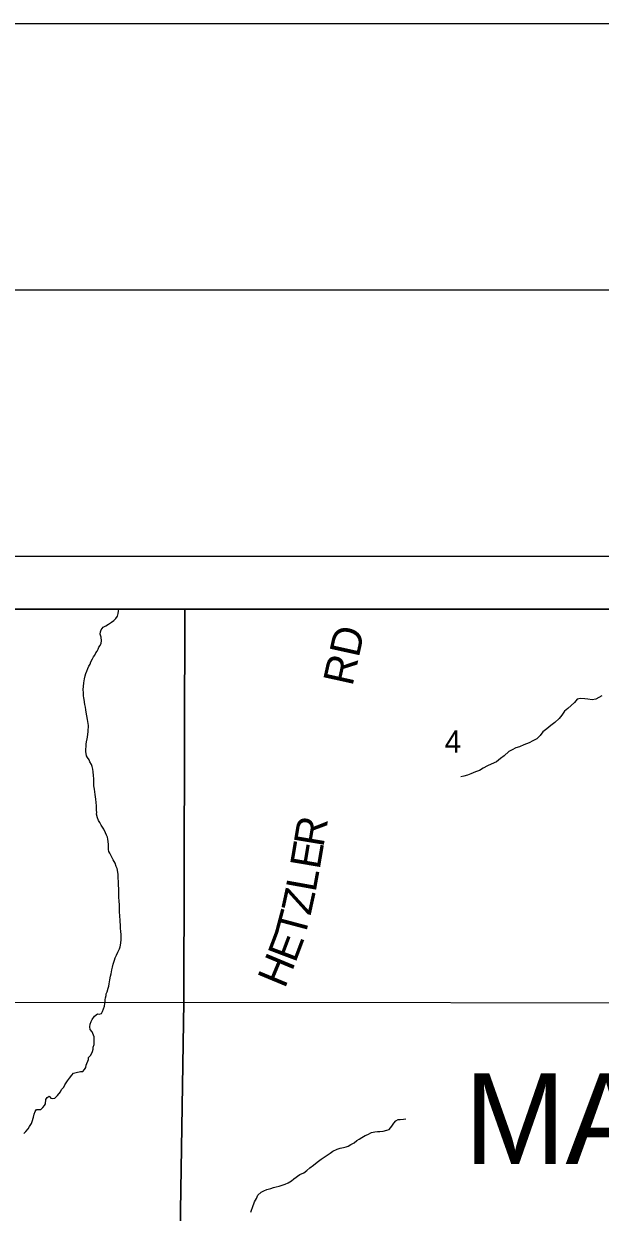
# Model space of a CAD drawing. Extents: x 0 to 34, y 0 to 22.
# Drawn here: x 3.881 to 4.964, y 19.765 to 21.998 of the extents above; entities that cross this region are included whole.
import ezdxf

# ---------------------------------------------------------------- set-up
doc = ezdxf.new("R2010")
doc.units = 0
for name, color, linetype in [('GM_X_Corporation', 7, 'Continuous'), ('GM_X_Minor_River', 7, 'Continuous'), ('GM_X_Section_Text', 7, 'Continuous'), ('GM_X_Township_Road_Text', 7, 'Continuous'), ('GM_X_Township_Text', 7, 'Continuous'), ('SH_Border', 7, 'Continuous'), ('SH_Cut_Line', 7, 'Continuous'), ('SH_Data', 7, 'Continuous')]:
    doc.layers.add(name, color=color, linetype=linetype)

msp = doc.modelspace()

# ---------------------------------------------------------------- linework, layer by layer
at = {"layer": 'GM_X_Corporation'}
msp.add_lwpolyline([(8.2346, 19.7113), (8.2412, 20.0451), (8.2424, 20.1172), (8.2437, 20.1914), (8.2459, 20.3463), (8.2498, 20.6242), (8.2532, 20.898), (2.1, 20.898)], dxfattribs=at)
for points in [[(4.1833, 20.898), (3.1749, 20.898), (3.1676, 20.1592), (4.1816, 20.1598)], [(5.1975, 20.898), (4.1833, 20.898), (4.1816, 20.1598), (5.1838, 20.1584)], [(3.1676, 20.1592), (4.1816, 20.1598), (4.1654, 19.1412), (3.1497, 19.1471)], [(5.1838, 20.1584), (5.1759, 19.1377), (4.1654, 19.1412), (4.1816, 20.1598)]]:
    msp.add_lwpolyline(points, close=True, dxfattribs=at)
at = {"layer": 'GM_X_Minor_River'}
for points in [[(4.0263, 20.8346), (4.0272, 20.8387), (4.0262, 20.8456), (4.0248, 20.8513), (4.0249, 20.8555), (4.0262, 20.8592), (4.0301, 20.8645), (4.0351, 20.867), (4.0405, 20.8699), (4.0456, 20.8739), (4.0499, 20.8772), (4.0541, 20.8809), (4.0573, 20.8853), (4.0586, 20.8899), (4.0591, 20.8948), (4.0594, 20.898)], [(4.0631, 20.293), (4.0628, 20.2987), (4.0626, 20.3037), (4.062, 20.312), (4.0621, 20.3154), (4.0615, 20.3204), (4.061, 20.3318), (4.0611, 20.3356), (4.0606, 20.3428), (4.06, 20.3497), (4.0598, 20.3572), (4.0593, 20.3652), (4.0595, 20.3736), (4.0592, 20.3789), (4.0587, 20.388), (4.0584, 20.3918), (4.0582, 20.396), (4.0583, 20.3998), (4.058, 20.404), (4.0563, 20.4109), (4.0549, 20.4147), (4.0524, 20.4208), (4.0491, 20.4274), (4.0455, 20.4351), (4.0426, 20.4397), (4.0411, 20.4432), (4.0405, 20.447), (4.0402, 20.4508), (4.0403, 20.4561), (4.0397, 20.4618), (4.0391, 20.4664), (4.0381, 20.4702), (4.0366, 20.4737), (4.0348, 20.4783), (4.0312, 20.4848), (4.0287, 20.4887), (4.0265, 20.4925), (4.0239, 20.4972), (4.0214, 20.5014), (4.0196, 20.5064), (4.0179, 20.5129), (4.018, 20.5163), (4.0177, 20.5209), (4.0179, 20.5288), (4.0169, 20.5353), (4.0163, 20.541), (4.015, 20.5498), (4.0138, 20.5601), (4.0128, 20.5662), (4.0126, 20.5715), (4.0124, 20.5795), (4.0122, 20.5856), (4.0116, 20.5928), (4.011, 20.5974), (4.0096, 20.6027), (4.0082, 20.6065), (4.0053, 20.6116), (4.0038, 20.6154), (4.0005, 20.6193), (3.9991, 20.6227), (3.9978, 20.6311), (3.9979, 20.6353), (3.998, 20.6402), (3.9981, 20.6444), (3.999, 20.6489), (3.9999, 20.6546), (4.0008, 20.658), (4.0022, 20.6682), (4.0025, 20.68), (4.0018, 20.6834), (4.0005, 20.691), (3.9995, 20.6979), (3.9982, 20.7048), (3.9975, 20.7089), (3.9969, 20.7139), (3.9959, 20.7189), (3.9942, 20.7284), (3.9936, 20.7318), (3.9933, 20.7356), (3.9931, 20.7413), (3.9928, 20.7474), (3.9934, 20.7531), (3.9939, 20.7599), (3.9944, 20.7637), (3.9953, 20.7675), (3.9965, 20.7728), (3.9978, 20.7777), (3.9998, 20.7818), (4.0015, 20.7867), (4.0035, 20.7912), (4.0055, 20.7949), (4.0071, 20.7994), (4.0103, 20.805), (4.0123, 20.8088), (4.0147, 20.8121), (4.0163, 20.8162), (4.0187, 20.8196), (4.0207, 20.823), (4.0223, 20.8267), (4.0243, 20.8301), (4.0263, 20.8346)], [(4.9407, 20.729), (4.9346, 20.7298), (4.9267, 20.7306), (4.9203, 20.7292), (4.9153, 20.7231), (4.9092, 20.7171), (4.9031, 20.7115), (4.8963, 20.7066), (4.8913, 20.6991), (4.8867, 20.693), (4.8783, 20.6851), (4.8707, 20.6795), (4.8631, 20.6735), (4.8559, 20.6675), (4.8506, 20.6611), (4.8445, 20.6547), (4.8369, 20.6506), (4.83, 20.6472), (4.8202, 20.6432), (4.8118, 20.6398), (4.8054, 20.6376), (4.7982, 20.6343), (4.7921, 20.6309), (4.783, 20.623), (4.7761, 20.6174), (4.7689, 20.6114), (4.7587, 20.6069), (4.7522, 20.6039), (4.7439, 20.5998), (4.737, 20.5954), (4.7294, 20.5924), (4.7207, 20.5887), (4.7146, 20.5865), (4.7078, 20.5846), (4.7018, 20.5832)], [(4.9664, 20.7356), (4.9554, 20.7292), (4.9486, 20.7281), (4.9407, 20.729)], [(3.8809, 19.9135), (3.8848, 19.9172), (3.8891, 19.922), (3.8918, 19.9265), (3.8954, 19.9321), (3.897, 19.9355), (3.8995, 19.9441), (3.9008, 19.9494), (3.9025, 19.9547), (3.9052, 19.958), (3.9094, 19.9583), (3.9132, 19.9582), (3.9171, 19.9622), (3.9199, 19.9656), (3.9219, 19.9689), (3.9228, 19.9773), (3.9248, 19.981), (3.9287, 19.9832), (3.932, 19.9797), (3.9354, 19.9788), (3.9396, 19.9795), (3.9443, 19.9846), (3.9498, 19.9917), (3.9518, 19.9958), (3.9561, 20.0003), (3.9582, 20.0048), (3.9633, 20.0122), (3.9672, 20.0174), (3.9712, 20.023), (3.9747, 20.0263), (3.9793, 20.0281), (3.9873, 20.0294), (3.9919, 20.03), (3.9954, 20.0333), (3.9974, 20.0375), (3.9983, 20.0416), (4.0024, 20.0525), (4.0029, 20.0559), (4.0064, 20.06), (4.0092, 20.0641), (4.01, 20.0675), (4.0113, 20.0716), (4.0117, 20.0754), (4.013, 20.0807), (4.0133, 20.0909), (4.013, 20.0951), (4.0094, 20.1039), (4.0058, 20.1086), (4.0051, 20.1135), (4.006, 20.1188), (4.0077, 20.1237), (4.0097, 20.1275), (4.014, 20.1334), (4.0195, 20.1378), (4.0229, 20.1374), (4.0271, 20.1384), (4.0291, 20.1421), (4.0328, 20.1523), (4.0333, 20.1576), (4.0338, 20.161), (4.0342, 20.1644), (4.0347, 20.1682), (4.0356, 20.1723), (4.036, 20.1757), (4.038, 20.1794), (4.0397, 20.1862), (4.0406, 20.19), (4.0415, 20.1945), (4.0424, 20.2021), (4.0437, 20.2085), (4.045, 20.2134), (4.0467, 20.221), (4.0476, 20.2259), (4.0489, 20.2315), (4.0514, 20.2387), (4.053, 20.2432), (4.0554, 20.2484), (4.0579, 20.2541), (4.0611, 20.26), (4.0623, 20.2642), (4.0636, 20.2706), (4.0642, 20.2778), (4.0637, 20.2869), (4.0631, 20.293)], [(4.3604, 19.8144), (4.368, 19.8166), (4.3721, 19.8181), (4.3774, 19.8207), (4.3839, 19.824), (4.3885, 19.8278), (4.3995, 19.836), (4.4071, 19.8394), (4.4128, 19.8439), (4.4185, 19.8488), (4.425, 19.854), (4.4318, 19.8593), (4.4394, 19.8649), (4.4451, 19.8686), (4.4508, 19.8728), (4.4565, 19.8765), (4.4614, 19.8799), (4.4694, 19.884), (4.4755, 19.8858), (4.4815, 19.8869), (4.4865, 19.8884), (4.4906, 19.8895), (4.4956, 19.8925), (4.5013, 19.8958), (4.5066, 19.9003), (4.5112, 19.9026), (4.5161, 19.9055), (4.5222, 19.9093), (4.5275, 19.9115), (4.5339, 19.9149), (4.5404, 19.9163), (4.5453, 19.917), (4.5495, 19.917), (4.5559, 19.9173), (4.5627, 19.9192), (4.5673, 19.9206), (4.5726, 19.927), (4.576, 19.9327), (4.5795, 19.9368), (4.584, 19.9394), (4.5882, 19.9398), (4.5939, 19.9401), (4.5984, 19.9408)], [(4.3075, 19.7652), (4.309, 19.7693), (4.3109, 19.7739), (4.3144, 19.7849), (4.3182, 19.7913), (4.3209, 19.7973), (4.327, 19.8033), (4.332, 19.8056), (4.3373, 19.8078), (4.3448, 19.81), (4.3498, 19.8115), (4.3551, 19.8129), (4.3604, 19.8144)]]:
    msp.add_lwpolyline(points, dxfattribs=at)
at = {"layer": 'SH_Border'}
msp.add_lwpolyline([(1.5, 21.498), (33.5, 21.498), (33.5, 0.498), (1.5, 0.498)], close=True, dxfattribs=at)
at = {"layer": 'SH_Cut_Line'}
msp.add_lwpolyline([(0, -0.002), (34, -0.002), (34, 21.998), (0, 21.998)], close=True, dxfattribs=at)
at = {"layer": 'SH_Data'}
for p, q in [((2, 20.998), (9, 20.998)), ((2.1, 20.898), (8.9, 20.898))]:
    msp.add_line(p, q, dxfattribs=at)

# ---------------------------------------------------------------- texts
at = {"layer": 'GM_X_Section_Text'}
msp.add_text('4', height=0.0419, rotation=0, dxfattribs=at).set_placement((4.6715, 20.6286))
at = {"layer": 'GM_X_Township_Road_Text'}
for s, height, rotation, p in [('RD', 0.05682, 77.5254, (4.4982, 20.7521)), ('R', 0.0568, 80.4811, (4.4437, 20.4496)), ('E', 0.0568, 80.4694, (4.4367, 20.4077)), ('L', 0.0568, 79.7876, (4.429, 20.3652)), ('Z', 0.0568, 77.6252, (4.4195, 20.3214)), ('T', 0.0568, 75.0974, (4.4079, 20.2777)), ('E', 0.0568, 69.3106, (4.391, 20.2321)), ('H', 0.0568, 67.4163, (4.3711, 20.184))]:
    msp.add_text(s, height=height, rotation=rotation, dxfattribs=at).set_placement(p)
at = {"layer": 'GM_X_Township_Text'}
msp.add_text('MADISON', height=0.17045, rotation=0, dxfattribs=at).set_placement((4.7086, 19.8561))

doc.saveas('drawing.dxf')
